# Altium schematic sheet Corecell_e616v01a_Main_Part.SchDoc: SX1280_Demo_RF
size B; DrawnBy: EMr; DocumentNumber: 1; SheetNumber: 1; SheetTotal: 3; PageSetup: Record=PageOptions¦CenterHorizontal=True¦CenterVertical=True¦PrintScale=0.72¦XCorrection=1.00¦YCorrection=1.00¦PrintKind=0¦BorderSize=5000000¦LeftOffset=0¦BottomOffset=0¦Orientation=2¦PaperLength=1000¦PaperWidth=1000¦Scale=100¦PaperSource=7¦PrintQuality=-4¦MediaType=1¦DitherType=10¦PaperKind=Letter¦PrintScaleMode=1
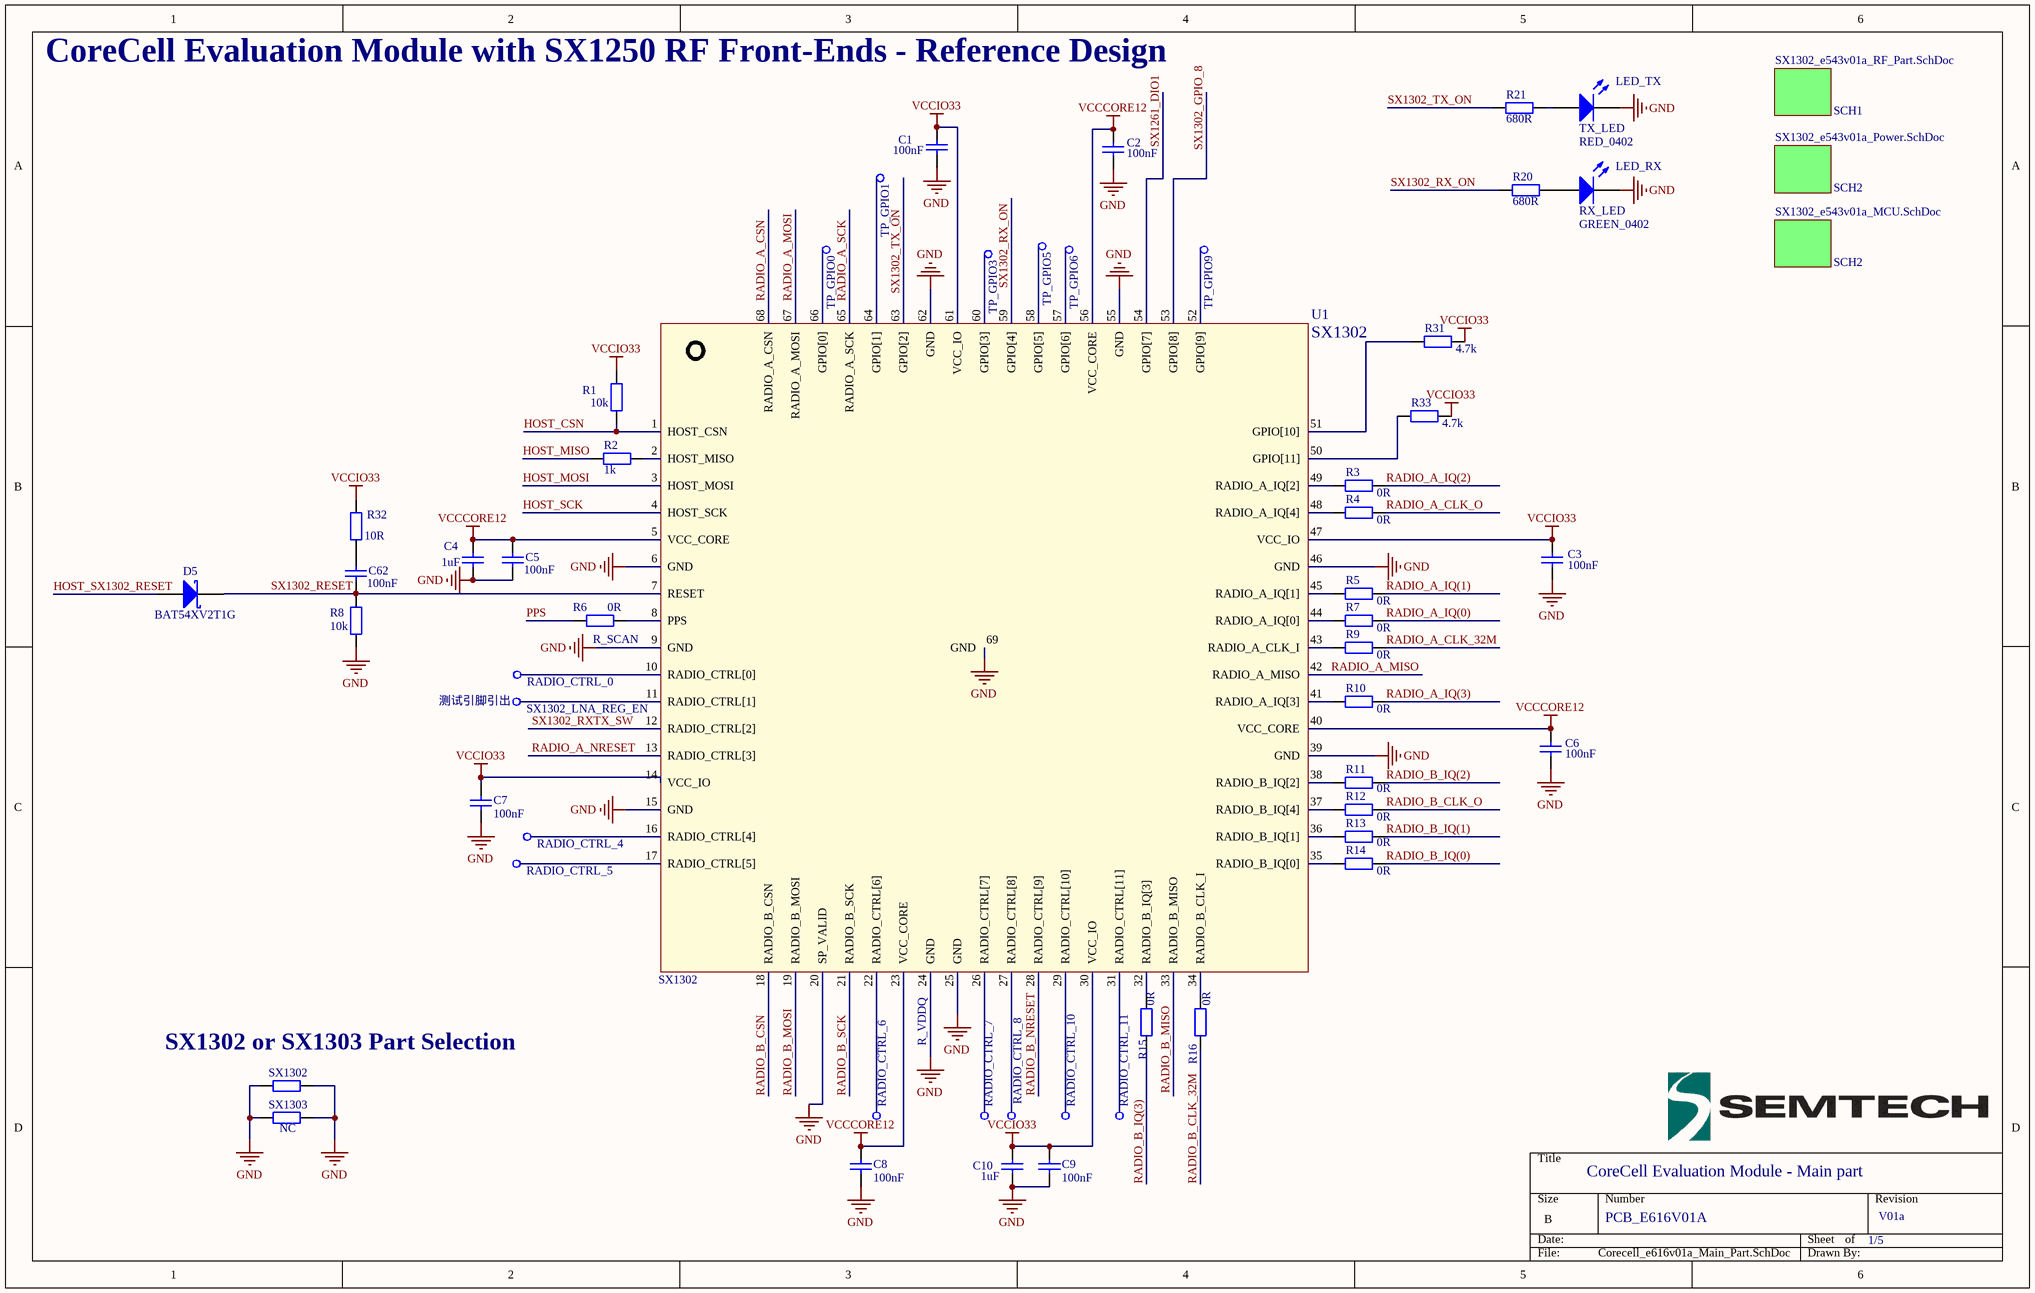
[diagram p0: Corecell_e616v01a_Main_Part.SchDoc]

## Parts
C1  value 100nF  [rlc_201_smd_small]  (hidden comment: Cap)
C2  value 100nF  [rlc_201_smd_small]  (hidden comment: Cap)
C3  value 100nF  [rlc_201_smd_small]  (hidden comment: Cap)
C4  value 1uF  [rlc_402_smd_small]  (hidden comment: Cap)
C5  value 100nF  [rlc_201_smd_small]  (hidden comment: Cap)
C6  value 100nF  [rlc_201_smd_small]  (hidden comment: Cap)
C7  value 100nF  [rlc_201_smd_small]  (hidden comment: Cap)
C8  value 100nF  [rlc_201_smd_small]  (hidden comment: Cap)
C9  value 100nF  [rlc_201_smd_small]  (hidden comment: Cap)
C10  value 1uF  [rlc_402_smd_small]  (hidden comment: Cap)
C62  value 100nF  [rlc_201_smd_small]  (hidden comment: Cap)
D5  value BAT54XV2T1G  [SOD523]  (hidden comment: D Schottky)
LED_RX  RX_LED  value GREEN_0402  [CD1005-0402]
LED_TX  TX_LED  value RED_0402  [CD1005-0402]
R1  value 10k  [rlc_201_smd_small]  (hidden comment: Resistor)
R2  value 1k  [rlc_201_smd_small]  (hidden comment: Resistor)
R3  value 0R  [rlc_201_smd_small]  (hidden comment: Resistor)
R4  value 0R  [rlc_201_smd_small]  (hidden comment: Resistor)
R5  value 0R  [rlc_201_smd_small]  (hidden comment: Resistor)
R6  value 0R  [rlc_201_smd_small]  (hidden comment: Resistor)
R7  value 0R  [rlc_201_smd_small]  (hidden comment: Resistor)
R8  value 10k  [rlc_201_smd_small]  (hidden comment: Resistor)
R9  value 0R  [rlc_201_smd_small]  (hidden comment: Resistor)
R10  value 0R  [rlc_201_smd_small]  (hidden comment: Resistor)
R11  value 0R  [rlc_201_smd_small]  (hidden comment: Resistor)
R12  value 0R  [rlc_201_smd_small]  (hidden comment: Resistor)
R13  value 0R  [rlc_201_smd_small]  (hidden comment: Resistor)
R14  value 0R  [rlc_201_smd_small]  (hidden comment: Resistor)
R15  value 0R  [rlc_201_smd_small]  (hidden comment: Resistor)
R16  value 0R  [rlc_201_smd_small]  (hidden comment: Resistor)
R20  value 680R  [rlc_402_smd_small]  (hidden comment: Resistor)
R21  value 680R  [rlc_402_smd_small]  (hidden comment: Resistor)
R31  value 4.7k  [rlc_201_smd_small]  (hidden comment: Resistor)
R32  value 10R  [rlc_201_smd_small]  (hidden comment: Resistor)
R33  value 4.7k  [rlc_201_smd_small]  (hidden comment: Resistor)
RADIO_CTRL_0  Test Pin  [PIN_SMD]  (value not drawn)
RADIO_CTRL_4  Test Pin  [PIN_SMD]  (value not drawn)
RADIO_CTRL_5  Test Pin  [PIN_SMD]  (value not drawn)
RADIO_CTRL_6  Test Pin  [PIN_SMD]  (value not drawn)
RADIO_CTRL_7  Test Pin  [PIN_SMD]  (value not drawn)
RADIO_CTRL_8  Test Pin  [PIN_SMD]  (value not drawn)
RADIO_CTRL_10  Test Pin  [PIN_SMD]  (value not drawn)
RADIO_CTRL_11  Test Pin  [PIN_SMD]  (value not drawn)
SX1302  Resistor  [rlc_402_smd_small]  (value not drawn)
SX1302_LNA_REG_EN  Test Pin  [PIN_SMD]  (value not drawn)
SX1303  value NC  [rlc_402_smd_small]  (hidden comment: Resistor)
TP_GPIO0  Test Pin  [PIN_SMD]  (value not drawn)
TP_GPIO1  Test Pin  [PIN_SMD]  (value not drawn)
TP_GPIO3  Test Pin  [PIN_SMD]  (value not drawn)
TP_GPIO5  Test Pin  [PIN_SMD]  (value not drawn)
TP_GPIO6  Test Pin  [PIN_SMD]  (value not drawn)
TP_GPIO9  Test Pin  [PIN_SMD]  (value not drawn)
U1  SX1302  [vqfn68_7x7mm]

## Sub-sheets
SCH1 = SX1302_e543v01a_RF_Part.SchDoc: no entries
SCH2 = SX1302_e543v01a_Power.SchDoc: no entries
SCH2 = SX1302_e543v01a_MCU.SchDoc: no entries

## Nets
GND: C1.1 C2.1 C3.1 C4.1 C5.1 C6.1 C7.1 C8.1 C9.1 C10.1 LED_RX.2(K) LED_TX.2(K) R8.1 SX1302.1 SX1302.2 SX1303.1 SX1303.2 U1.6(GND) U1.9(GND) U1.15(GND) U1.20(SP_VALID) U1.24(GND) U1.25(GND) U1.39(GND) U1.46(GND) U1.55(GND) U1.62(GND) U1.69(GND)
VCCCORE12: C2.2 C4.2 C5.2 C6.2 C8.2 U1.5(VCC_CORE) U1.23(VCC_CORE) U1.40(VCC_CORE) U1.56(VCC_CORE)
VCCIO33: C1.2 C3.2 C7.2 C9.2 C10.2 R1.2 R31.2 R32.2 R33.2 U1.14(VCC_IO) U1.30(VCC_IO) U1.47(VCC_IO) U1.61(VCC_IO)
HOST_CSN: R1.1 U1.1(HOST_CSN)
HOST_MISO: R2.2
HOST_MOSI: U1.3(HOST_MOSI)
HOST_SCK: U1.4(HOST_SCK)
HOST_SX1302_RESET: D5.1(A)
PPS: R6.1
RADIO_A_CLK_32M: R9.2
RADIO_A_CLK_O: R4.2
RADIO_A_CSN: U1.68(RADIO_A_CSN)
RADIO_A_IQ(0): R7.2
RADIO_A_IQ(1): R5.2
RADIO_A_IQ(2): R3.2
RADIO_A_IQ(3): R10.2
RADIO_A_MISO: U1.42(RADIO_A_MISO)
RADIO_A_MOSI: U1.67(RADIO_A_MOSI)
RADIO_A_NRESET: U1.13(RADIO_CTRL[3])
RADIO_A_SCK: U1.65(RADIO_A_SCK)
RADIO_B_CLK_32M: R16.1
RADIO_B_CLK_O: R12.2
RADIO_B_CSN: U1.18(RADIO_B_CSN)
RADIO_B_IQ(0): R14.2
RADIO_B_IQ(1): R13.2
RADIO_B_IQ(2): R11.2
RADIO_B_IQ(3): R15.1
RADIO_B_MISO: U1.33(RADIO_B_MISO)
RADIO_B_MOSI: U1.19(RADIO_B_MOSI)
RADIO_B_NRESET: U1.28(RADIO_CTRL[9])
RADIO_B_SCK: U1.21(RADIO_B_SCK)
SX1261_DIO1: U1.54(GPIO[7])
SX1302_GPIO_8: U1.53(GPIO[8])
SX1302_RESET: C62.1 D5.2(K) R8.2 U1.7(RESET)
SX1302_RX_ON: R20.1 U1.59(GPIO[4])
SX1302_RXTX_SW: U1.12(RADIO_CTRL[2])
SX1302_TX_ON: R21.2 U1.63(GPIO[2])
NetC62_2: C62.2 R32.1
NetLED_RX_1: LED_RX.1(A) R20.2
NetLED_TX_1: LED_TX.1(A) R21.1
NetR2_1: R2.1 U1.2(HOST_MISO)
NetR3_1: R3.1 U1.49(RADIO_A_IQ[2])
NetR4_1: R4.1 U1.48(RADIO_A_IQ[4])
NetR5_1: R5.1 U1.45(RADIO_A_IQ[1])
NetR6_2: R6.2 U1.8(PPS)
NetR7_1: R7.1 U1.44(RADIO_A_IQ[0])
NetR9_1: R9.1 U1.43(RADIO_A_CLK_I)
NetR10_1: R10.1 U1.41(RADIO_A_IQ[3])
NetR11_1: R11.1 U1.38(RADIO_B_IQ[2])
NetR12_1: R12.1 U1.37(RADIO_B_IQ[4])
NetR13_1: R13.1 U1.36(RADIO_B_IQ[1])
NetR14_1: R14.1 U1.35(RADIO_B_IQ[0])
NetR15_2: R15.2 U1.32(RADIO_B_IQ[3])
NetR16_2: R16.2 U1.34(RADIO_B_CLK_I)
NetR31_1: R31.1 U1.51(GPIO[10])
NetR33_1: R33.1 U1.50(GPIO[11])
NetRADIO_CTRL_0_1: RADIO_CTRL_0.1(pin) U1.10(RADIO_CTRL[0])
NetRADIO_CTRL_4_1: RADIO_CTRL_4.1(pin) U1.16(RADIO_CTRL[4])
NetRADIO_CTRL_5_1: RADIO_CTRL_5.1(pin) U1.17(RADIO_CTRL[5])
NetRADIO_CTRL_6_1: RADIO_CTRL_6.1(pin) U1.22(RADIO_CTRL[6])
NetRADIO_CTRL_7_1: RADIO_CTRL_7.1(pin) U1.26(RADIO_CTRL[7])
NetRADIO_CTRL_8_1: RADIO_CTRL_8.1(pin) U1.27(RADIO_CTRL[8])
NetRADIO_CTRL_10_1: RADIO_CTRL_10.1(pin) U1.29(RADIO_CTRL[10])
NetRADIO_CTRL_11_1: RADIO_CTRL_11.1(pin) U1.31(RADIO_CTRL[11])
NetSX1302_LNA_REG_EN_1: SX1302_LNA_REG_EN.1(pin) U1.11(RADIO_CTRL[1])
NetTP_GPIO0_1: TP_GPIO0.1(pin) U1.66(GPIO[0])
NetTP_GPIO1_1: TP_GPIO1.1(pin) U1.64(GPIO[1])
NetTP_GPIO3_1: TP_GPIO3.1(pin) U1.60(GPIO[3])
NetTP_GPIO5_1: TP_GPIO5.1(pin) U1.58(GPIO[5])
NetTP_GPIO6_1: TP_GPIO6.1(pin) U1.57(GPIO[6])
NetTP_GPIO9_1: TP_GPIO9.1(pin) U1.52(GPIO[9])

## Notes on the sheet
- CoreCell Evaluation Module with SX1250 RF Front-Ends - Reference Design
- 测试引脚引出
- (near R6) R_SCAN
- (near U1) R_VDDQ
- (near SX1302) SX1302 or SX1303 Part Selection
- CoreCell Evaluation Module - Main part
- PCB_E616V01A
- 1/5
- V01a

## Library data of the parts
C1-C10 C62 = Cap: Capacitor SMD
D5 = D Schottky: Schottky Diode
LED_RX LED_TX = LED
R1-R16 R20 R21 R31-R33 SX1303 = Resistor: Resistor SMD - IEC symbol version
RADIO_CTRL_0 RADIO_CTRL_4-RADIO_CTRL_8 RADIO_CTRL_10 RADIO_CTRL_11 SX1302_LNA_REG_EN TP_GPIO0 TP_GPIO1 TP_GPIO3 TP_GPIO5 TP_GPIO6 TP_GPIO9 = test_pin
SX1302 = Resistor: Resistor SMD - IEC symbol version; Value: 0R
U1 = SX1302: SX1302 - Base Band Processor for Data Concentrator for Long Range Communication Network;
